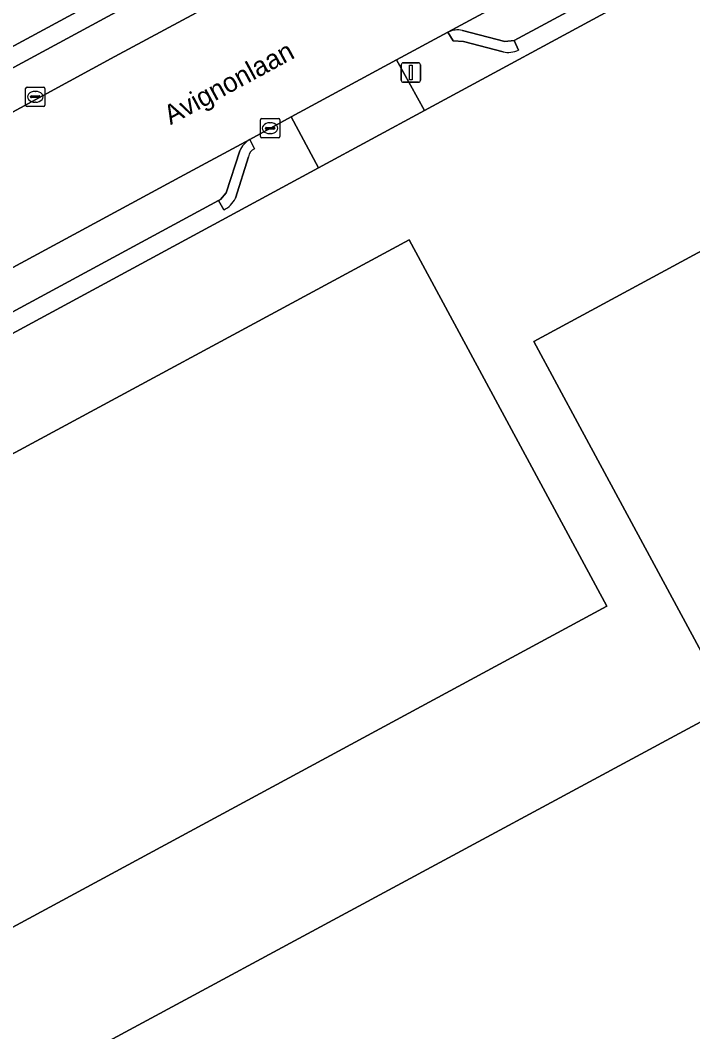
# Model space of a CAD drawing. Extents: x 158455 to 159797, y 387218 to 388672.
# Drawn here: x 158874.8 to 158909.4, y 387495.2 to 387547.3 of the extents above; entities that cross this region are included whole.
import ezdxf

# ---------------------------------------------------------------- set-up
doc = ezdxf.new("R2010")
doc.units = 0
for name, color, linetype in [('IMGEO_Erf', 7, 'Continuous'), ('IMGEO_Kolk', 7, 'Continuous'), ('IMGEO_Lichtmast', 7, 'Continuous'), ('IMGEO_Openbare_ruimte_label', 7, 'Continuous'), ('IMGEO_Pand', 7, 'Continuous'), ('IMGEO_Parkeervlak_open', 7, 'Continuous'), ('IMGEO_Rijbaan_lokaal_gesloten', 7, 'Continuous'), ('IMGEO_Voetpad_open', 7, 'Continuous')]:
    doc.layers.add(name, color=color, linetype=linetype)

msp = doc.modelspace()

# ---------------------------------------------------------------- linework, layer by layer
at = {"layer": 'IMGEO_Erf'}
for points in [[(158846.818, 387530.86), (158847.833, 387531.48), (158847.816, 387531.599), (158848.52, 387531.987), (158851.406, 387533.579), (158858.436, 387537.393), (158866.168, 387541.574), (158870.999, 387544.18), (158882.388, 387550.334), (158887.505, 387553.107), (158891.861, 387555.484), (158900.229, 387559.984), (158912.523, 387566.605), (158916.03, 387568.516), (158941.178, 387582.1)], [(158905.98, 387548.289), (158895.605, 387542.69), (158890.133, 387539.73), (158856.003, 387521.27)], [(158910.681, 387494.573), (158898.749, 387488.149), (158900.055, 387485.717), (158895.687, 387483.369), (158894.367, 387485.79), (158886.683, 387481.656), (158886.246, 387482.453), (158885, 387481.898), (158881.89, 387489.276), (158881.717, 387489.193), (158878.849, 387494.465), (158883.251, 387496.837), (158889.122, 387500), (158911.389, 387511.996), (158903.617, 387526.376), (158901.241, 387530.775), (158918.572, 387540.133)], [(158864.505, 387510.728), (158865.578, 387511.308), (158864.361, 387513.571), (158864.554, 387513.675), (158861.865, 387518.678), (158871.507, 387523.86), (158871.677, 387523.541), (158894.815, 387536.024), (158905.01, 387517.129), (158873.264, 387500), (158872.202, 387499.427)]]:
    msp.add_lwpolyline(points, dxfattribs=at)
at = {"layer": 'IMGEO_Kolk'}
for p, q in [((158875.027, 387542.966), (158875.027, 387543.818)), ((158875.102, 387543.892), (158875.954, 387543.892)), ((158876.028, 387543.818), (158876.028, 387542.966)), ((158875.286, 387543.386), (158875.286, 387543.398)), ((158875.724, 387543.349), (158875.326, 387543.349)), ((158875.329, 387543.435), (158875.727, 387543.435)), ((158875.515, 387543.672), (158875.54, 387543.672)), ((158875.77, 387543.398), (158875.77, 387543.386)), ((158875.954, 387542.892), (158875.102, 387542.892)), ((158875.538, 387543.112), (158875.513, 387543.112)), ((158887.214, 387542.271), (158888.066, 387542.271)), ((158887.139, 387541.345), (158887.139, 387542.197)), ((158887.398, 387541.765), (158887.398, 387541.777)), ((158887.836, 387541.728), (158887.438, 387541.728)), ((158887.441, 387541.814), (158887.839, 387541.814)), ((158887.627, 387542.051), (158887.652, 387542.051)), ((158887.882, 387541.777), (158887.882, 387541.765)), ((158888.14, 387542.197), (158888.14, 387541.345)), ((158888.066, 387541.271), (158887.214, 387541.271)), ((158887.65, 387541.491), (158887.625, 387541.491))]:
    msp.add_line(p, q, dxfattribs=at)
for points in [[(158875.027, 387542.966), (158875.027, 387543.818)], [(158875.102, 387543.892), (158875.954, 387543.892)], [(158876.028, 387543.818), (158876.028, 387542.966)], [(158875.954, 387542.892), (158875.102, 387542.892)], [(158887.214, 387542.271), (158888.066, 387542.271)], [(158887.139, 387541.345), (158887.139, 387542.197)], [(158888.14, 387542.197), (158888.14, 387541.345)], [(158888.066, 387541.271), (158887.214, 387541.271)]]:
    msp.add_lwpolyline(points, dxfattribs=at)
for centre, radius, start, end in [((158875.104, 387543.816), 0.0765, 91.552, 178.448), ((158875.104, 387543.816), 0.0765, 91.552, 178.448), ((158875.952, 387543.816), 0.0765, 1.552, 88.448), ((158875.952, 387543.816), 0.0765, 1.552, 88.448), ((158875.326, 387543.395), 0.0403, 85.8775, 175.7526), ((158875.323, 387543.385), 0.0366, 178.938, 274.7102), ((158875.727, 387543.392), 0.043, 264.8664, 352.4533), ((158875.731, 387543.397), 0.0386, 1.7309, 96.639), ((158875.104, 387542.968), 0.0765, 181.552, 268.448), ((158875.104, 387542.968), 0.0765, 181.552, 268.448), ((158875.952, 387542.968), 0.0765, 271.552, 358.448), ((158875.952, 387542.968), 0.0765, 271.552, 358.448), ((158887.216, 387542.195), 0.0765, 91.552, 178.448), ((158887.216, 387542.195), 0.0765, 91.552, 178.448), ((158888.064, 387542.195), 0.0765, 1.552, 88.448), ((158888.064, 387542.195), 0.0765, 1.552, 88.448), ((158887.438, 387541.774), 0.0403, 85.8775, 175.7526), ((158887.435, 387541.764), 0.0366, 178.938, 274.7102), ((158887.839, 387541.771), 0.043, 264.8664, 352.4533), ((158887.843, 387541.776), 0.0386, 1.7309, 96.639), ((158887.216, 387541.347), 0.0765, 181.552, 268.448), ((158887.216, 387541.347), 0.0765, 181.552, 268.448), ((158888.064, 387541.347), 0.0765, 271.552, 358.448), ((158888.064, 387541.347), 0.0765, 271.552, 358.448)]:
    msp.add_arc(centre, radius, start, end, dxfattribs=at)
for centre, major_axis, ratio, start_param, end_param in [((158875.514, 387543.392), (-0.387, 0.002), 0.722429, 4.712389, 7.853982), ((158875.539, 387543.392), (-0.39, 0.002), 0.717154, 1.570796, 4.712389), ((158887.626, 387541.771), (-0.387, 0.002), 0.722429, 4.712389, 7.853982), ((158887.651, 387541.771), (-0.39, 0.002), 0.717154, 1.570796, 4.712389)]:
    msp.add_ellipse(centre, major_axis=major_axis, ratio=ratio, start_param=start_param, end_param=end_param, dxfattribs=at)
at = {"layer": 'IMGEO_Lichtmast'}
for p, q in [((158894.402, 387544.242), (158894.402, 387545.042)), ((158894.402, 387545.042), (158894.402, 387544.242)), ((158894.502, 387545.142), (158895.292, 387545.142)), ((158895.292, 387545.142), (158894.502, 387545.142)), ((158895.392, 387545.042), (158895.392, 387544.242)), ((158895.392, 387544.242), (158895.392, 387545.042)), ((158895.292, 387544.142), (158894.502, 387544.142)), ((158894.502, 387544.142), (158895.292, 387544.142))]:
    msp.add_line(p, q, dxfattribs=at)
msp.add_lwpolyline([(158894.822, 387545.017), (158894.972, 387545.017), (158894.972, 387544.267), (158894.822, 387544.267), (158894.822, 387545.017)], dxfattribs=at)
for centre, start, end in [((158894.502, 387545.042), 90, 180), ((158894.502, 387545.042), 90, 180), ((158895.292, 387545.042), 0, 90), ((158895.292, 387545.042), 360, 90), ((158894.502, 387544.242), 180, 270), ((158894.502, 387544.242), 180, 270), ((158895.292, 387544.242), 270, 0), ((158895.292, 387544.242), 270, 0)]:
    msp.add_arc(centre, 0.1, start, end, dxfattribs=at)
at = {"layer": 'IMGEO_Pand'}
for points in [[(158918.572, 387540.133), (158901.241, 387530.775), (158903.617, 387526.376), (158911.389, 387511.996), (158889.122, 387500), (158883.251, 387496.837), (158878.849, 387494.465), (158881.717, 387489.193), (158881.89, 387489.276), (158885, 387481.898), (158886.246, 387482.453), (158886.683, 387481.656), (158894.367, 387485.79), (158895.687, 387483.369), (158900.055, 387485.717), (158898.749, 387488.149), (158910.681, 387494.573)], [(158865.966, 387508.085), (158867.179, 387508.739), (158871.893, 387500), (158872.202, 387499.427), (158873.264, 387500), (158905.01, 387517.129), (158894.815, 387536.024), (158871.677, 387523.541), (158871.507, 387523.86), (158861.865, 387518.678), (158864.554, 387513.675), (158864.361, 387513.571), (158865.578, 387511.308), (158864.505, 387510.728)]]:
    msp.add_lwpolyline(points, dxfattribs=at)
at = {"layer": 'IMGEO_Parkeervlak_open'}
for points in [[(158897.56, 387546.804), (158899.753, 387546.25), (158900.227, 387546.296), (158905.479, 387549.127), (158904.517, 387550.876), (158896.816, 387546.723)], [(158886.59, 387541.192), (158882.979, 387539.241), (158856.71, 387525.049)], [(158873.796, 387533.298), (158874.339, 387532.281), (158884.986, 387538.046), (158885.081, 387538.096), (158885.378, 387538.432), (158886.071, 387540.602)]]:
    msp.add_lwpolyline(points, dxfattribs=at)
msp.add_lwpolyline([(158883.827, 387547.727), (158882.862, 387549.484), (158871.462, 387543.325), (158872.408, 387541.551), (158879.639, 387545.462)], close=True, dxfattribs=at)
for centre, radius, start, end in [((158897.293, 387545.802), 1.037, 75.0666, 117.3602), ((158887.288, 387540.055), 1.334, 121.534, 155.7924)]:
    msp.add_arc(centre, radius, start, end, dxfattribs=at)
at = {"layer": 'IMGEO_Rijbaan_lokaal_gesloten'}
for points in [[(158938.034, 387568.981), (158945.261, 387573.028), (158942.09, 387579.183), (158938.179, 387577.074), (158925.645, 387570.477), (158925.408, 387570.184), (158924.776, 387569.835), (158924.362, 387569.798), (158917.496, 387565.904), (158913.917, 387563.975), (158901.619, 387557.339), (158893.251, 387552.841), (158888.915, 387550.505), (158883.827, 387547.727), (158879.639, 387545.462), (158872.408, 387541.551), (158867.599, 387538.947), (158860.225, 387535.032), (158859.898, 387534.793), (158848.286, 387528.465), (158847.453, 387527.845), (158846.663, 387527.069), (158846.092, 387526.338), (158846.011, 387526.246)], [(158854.513, 387523.859), (158856.71, 387525.049), (158882.979, 387539.241), (158886.59, 387541.192), (158888.726, 387542.365), (158894.162, 387545.301), (158896.816, 387546.723), (158904.517, 387550.876), (158909.82, 387553.755), (158920.733, 387559.66), (158926.582, 387562.826), (158938.034, 387568.981)]]:
    msp.add_lwpolyline(points, dxfattribs=at)
at = {"layer": 'IMGEO_Voetpad_open'}
for points in [[(158882.862, 387549.484), (158882.388, 387550.334), (158870.999, 387544.18), (158871.462, 387543.325)], [(158888.726, 387542.365), (158890.133, 387539.73), (158895.605, 387542.69), (158894.162, 387545.301)]]:
    msp.add_lwpolyline(points, close=True, dxfattribs=at)
for points in [[(158899.655, 387545.712), (158897.611, 387546.237), (158897.081, 387546.271), (158896.816, 387546.723), (158894.162, 387545.301), (158895.605, 387542.69), (158905.98, 387548.289), (158905.479, 387549.127), (158900.227, 387546.296), (158900.455, 387545.797)], [(158896.816, 387546.723), (158897.081, 387546.271), (158897.611, 387546.237), (158899.655, 387545.712)], [(158900.455, 387545.797), (158900.227, 387546.296), (158899.753, 387546.25), (158897.56, 387546.804)], [(158890.133, 387539.73), (158888.726, 387542.365), (158886.59, 387541.192), (158886.832, 387540.714)], [(158886.832, 387540.714), (158886.59, 387541.192)], [(158886.071, 387540.602), (158885.378, 387538.432), (158885.081, 387538.096), (158884.986, 387538.046), (158885.248, 387537.557)], [(158886.534, 387540.301), (158885.849, 387538.166)], [(158885.849, 387538.166), (158886.534, 387540.301)], [(158856.003, 387521.27), (158890.133, 387539.73)], [(158885.248, 387537.557), (158884.986, 387538.046), (158874.339, 387532.281), (158874.25, 387531.991), (158872.919, 387531.27), (158872.632, 387531.361), (158860.11, 387524.603), (158860.364, 387524.119)]]:
    msp.add_lwpolyline(points, dxfattribs=at)
for centre, radius, start, end in [((158897.293, 387545.802), 1.037, 75.0666, 117.3602), ((158899.933, 387546.906), 1.226, 256.9131, 295.2167), ((158899.933, 387546.906), 1.226, 256.9131, 295.2167), ((158887.288, 387540.055), 1.334, 121.534, 155.7924), ((158887.049, 387540.244), 0.518, 114.746, 173.6294), ((158887.049, 387540.244), 0.518, 114.746, 173.6294), ((158884.706, 387538.693), 1.258, 295.503, 335.2546), ((158884.706, 387538.693), 1.258, 295.503, 335.2546)]:
    msp.add_arc(centre, radius, start, end, dxfattribs=at)

# ---------------------------------------------------------------- texts
at = {"layer": 'IMGEO_Openbare_ruimte_label'}
msp.add_text('Avignonlaan', height=1, rotation=28.4366, dxfattribs=at).set_placement((158882.506, 387541.922))

doc.saveas('drawing.dxf')
